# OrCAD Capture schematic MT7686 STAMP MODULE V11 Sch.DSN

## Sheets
1 10_BB_RF: size C; title: MT7686 Stamp Module; rev: 1.1; company: MediaTek Inc.; note: 10_BB_RF
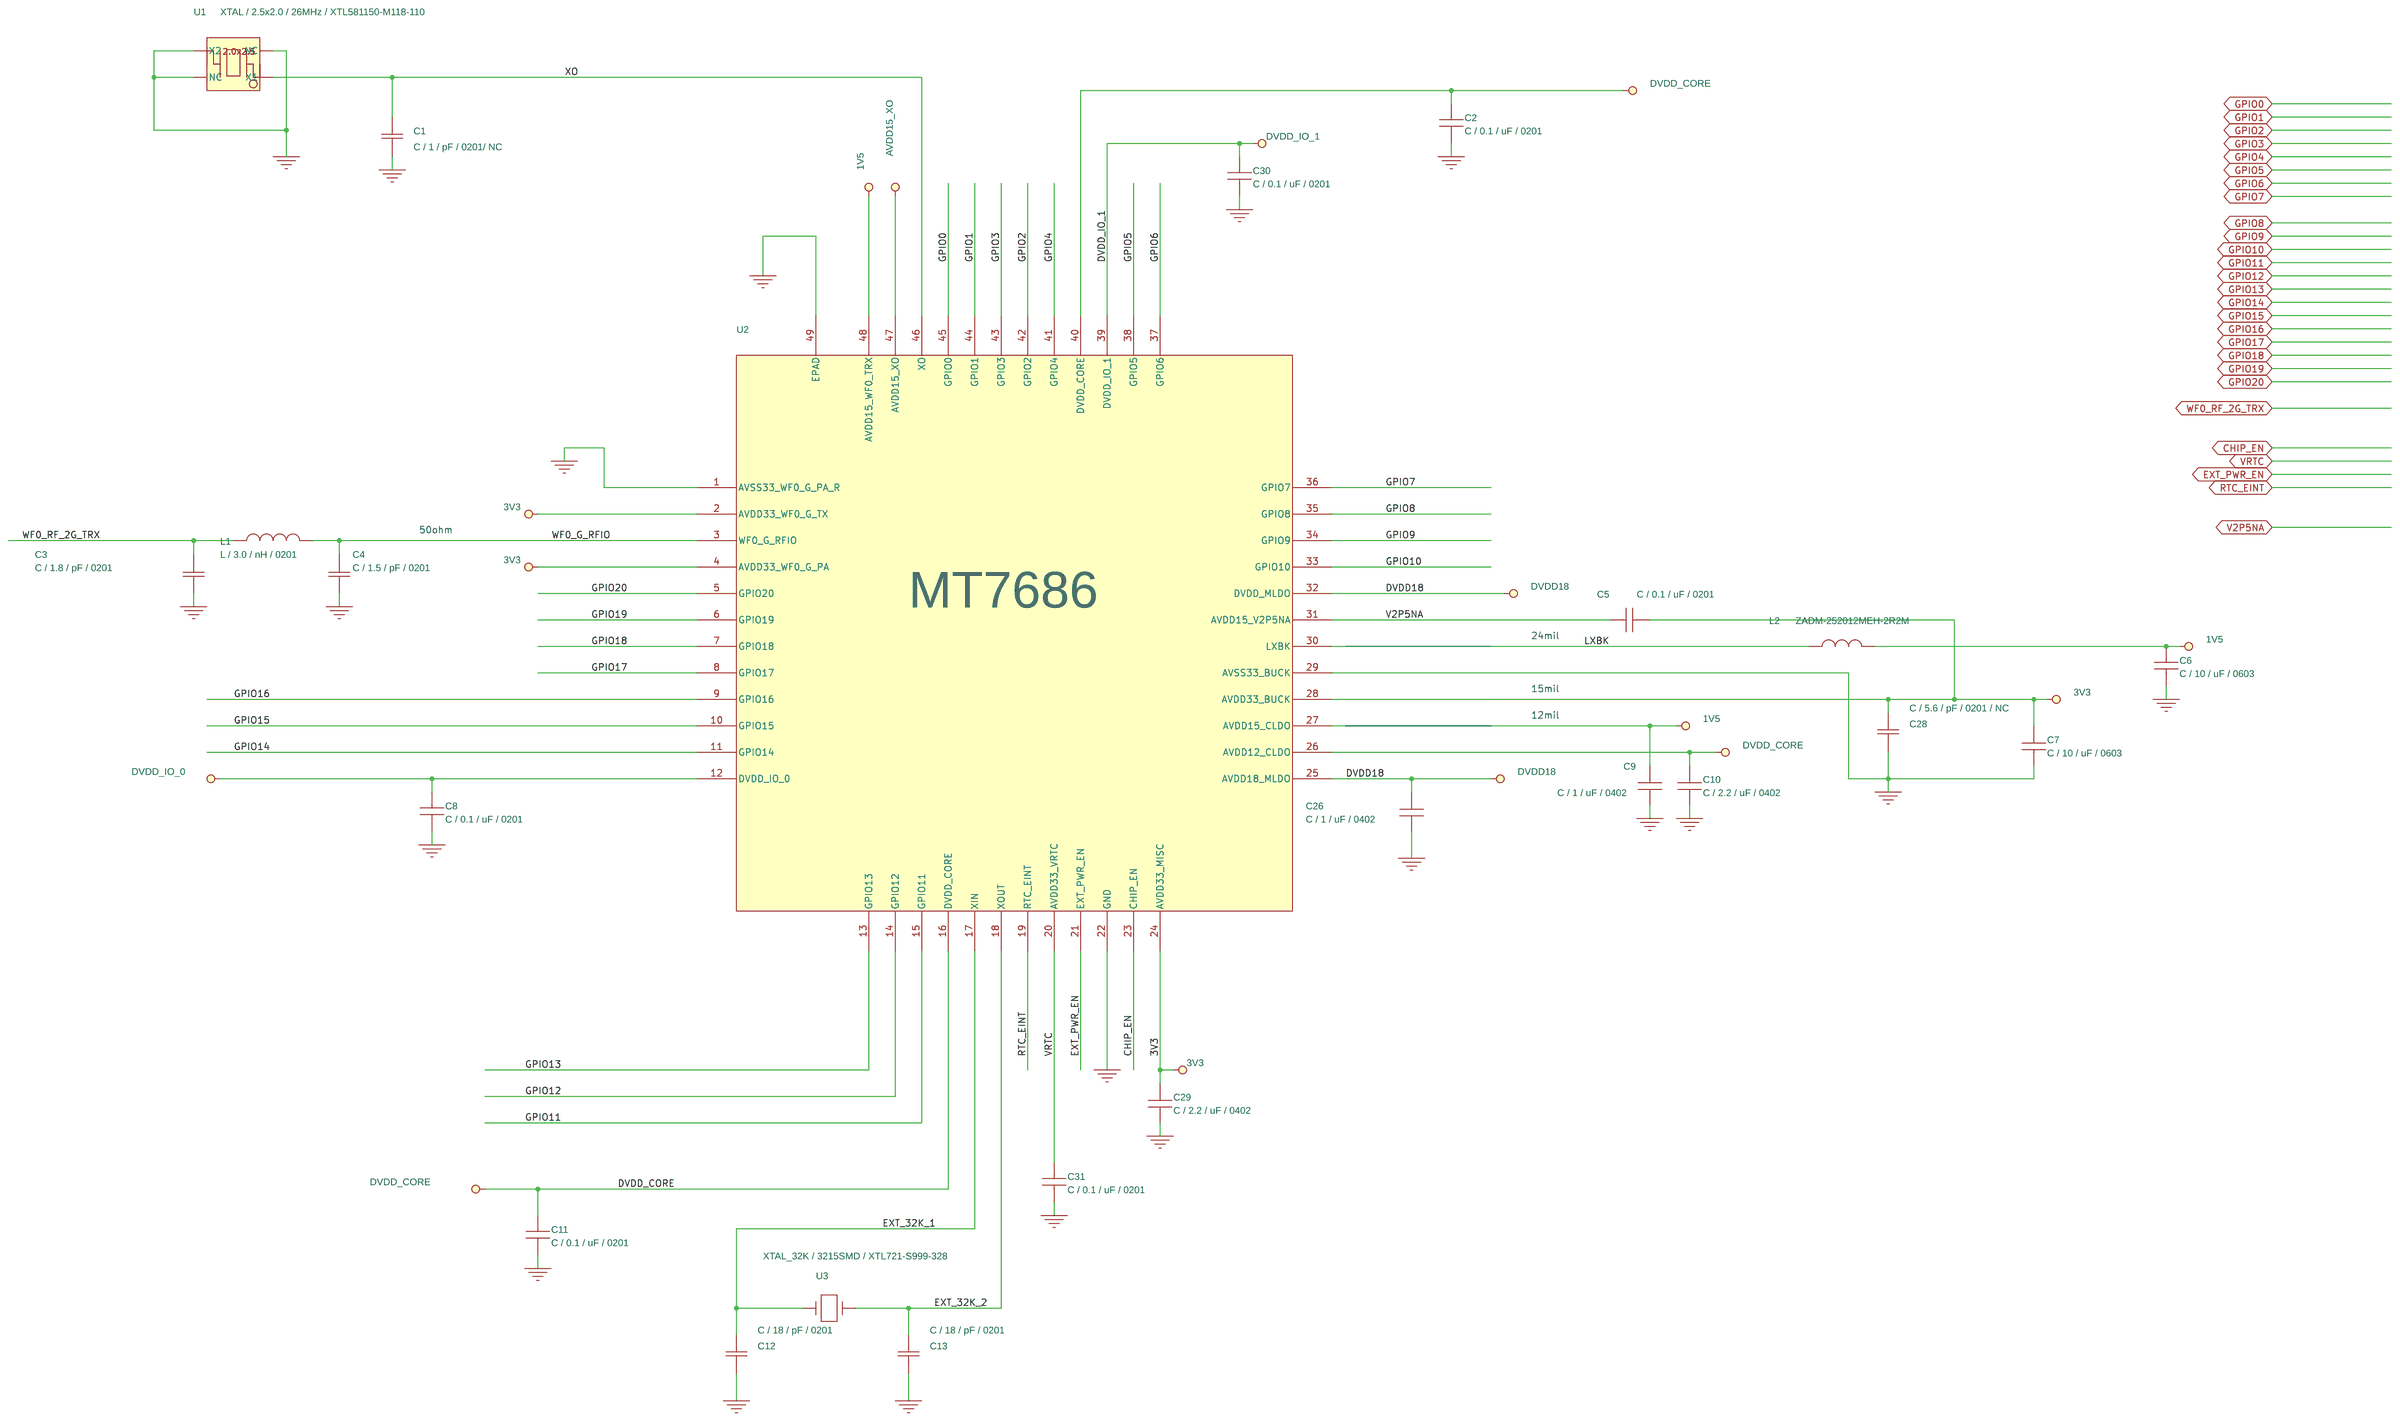
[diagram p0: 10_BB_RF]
2 20_RF Antenna and Connector: size C; note: 20_RF Antenna and Connector
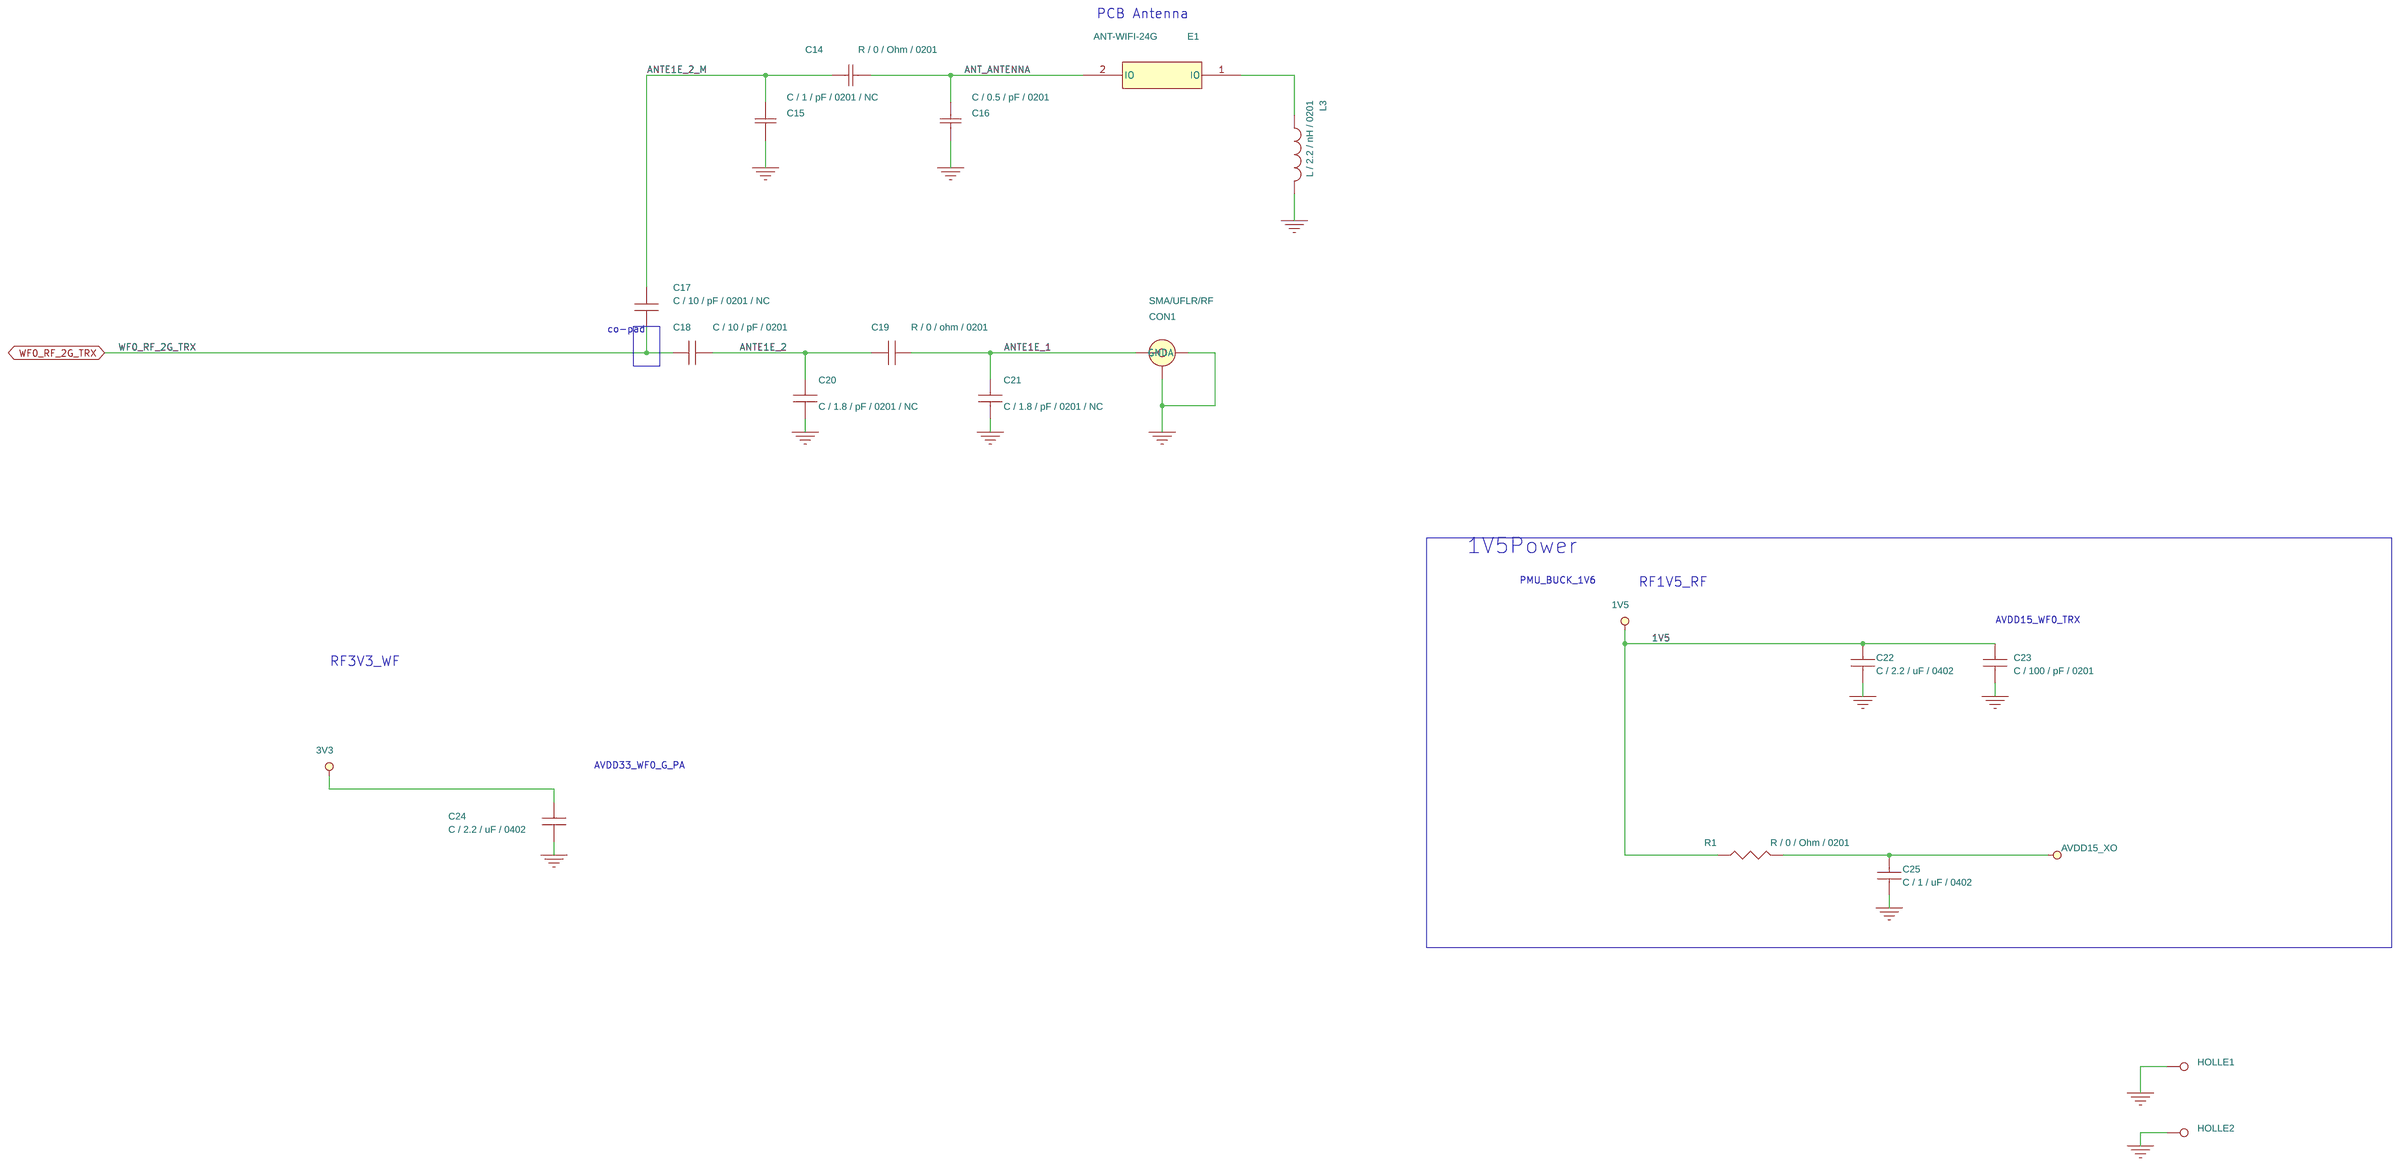
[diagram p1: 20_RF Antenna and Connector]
3 21_Strap and Module: size C; note: 21_Strap and Module
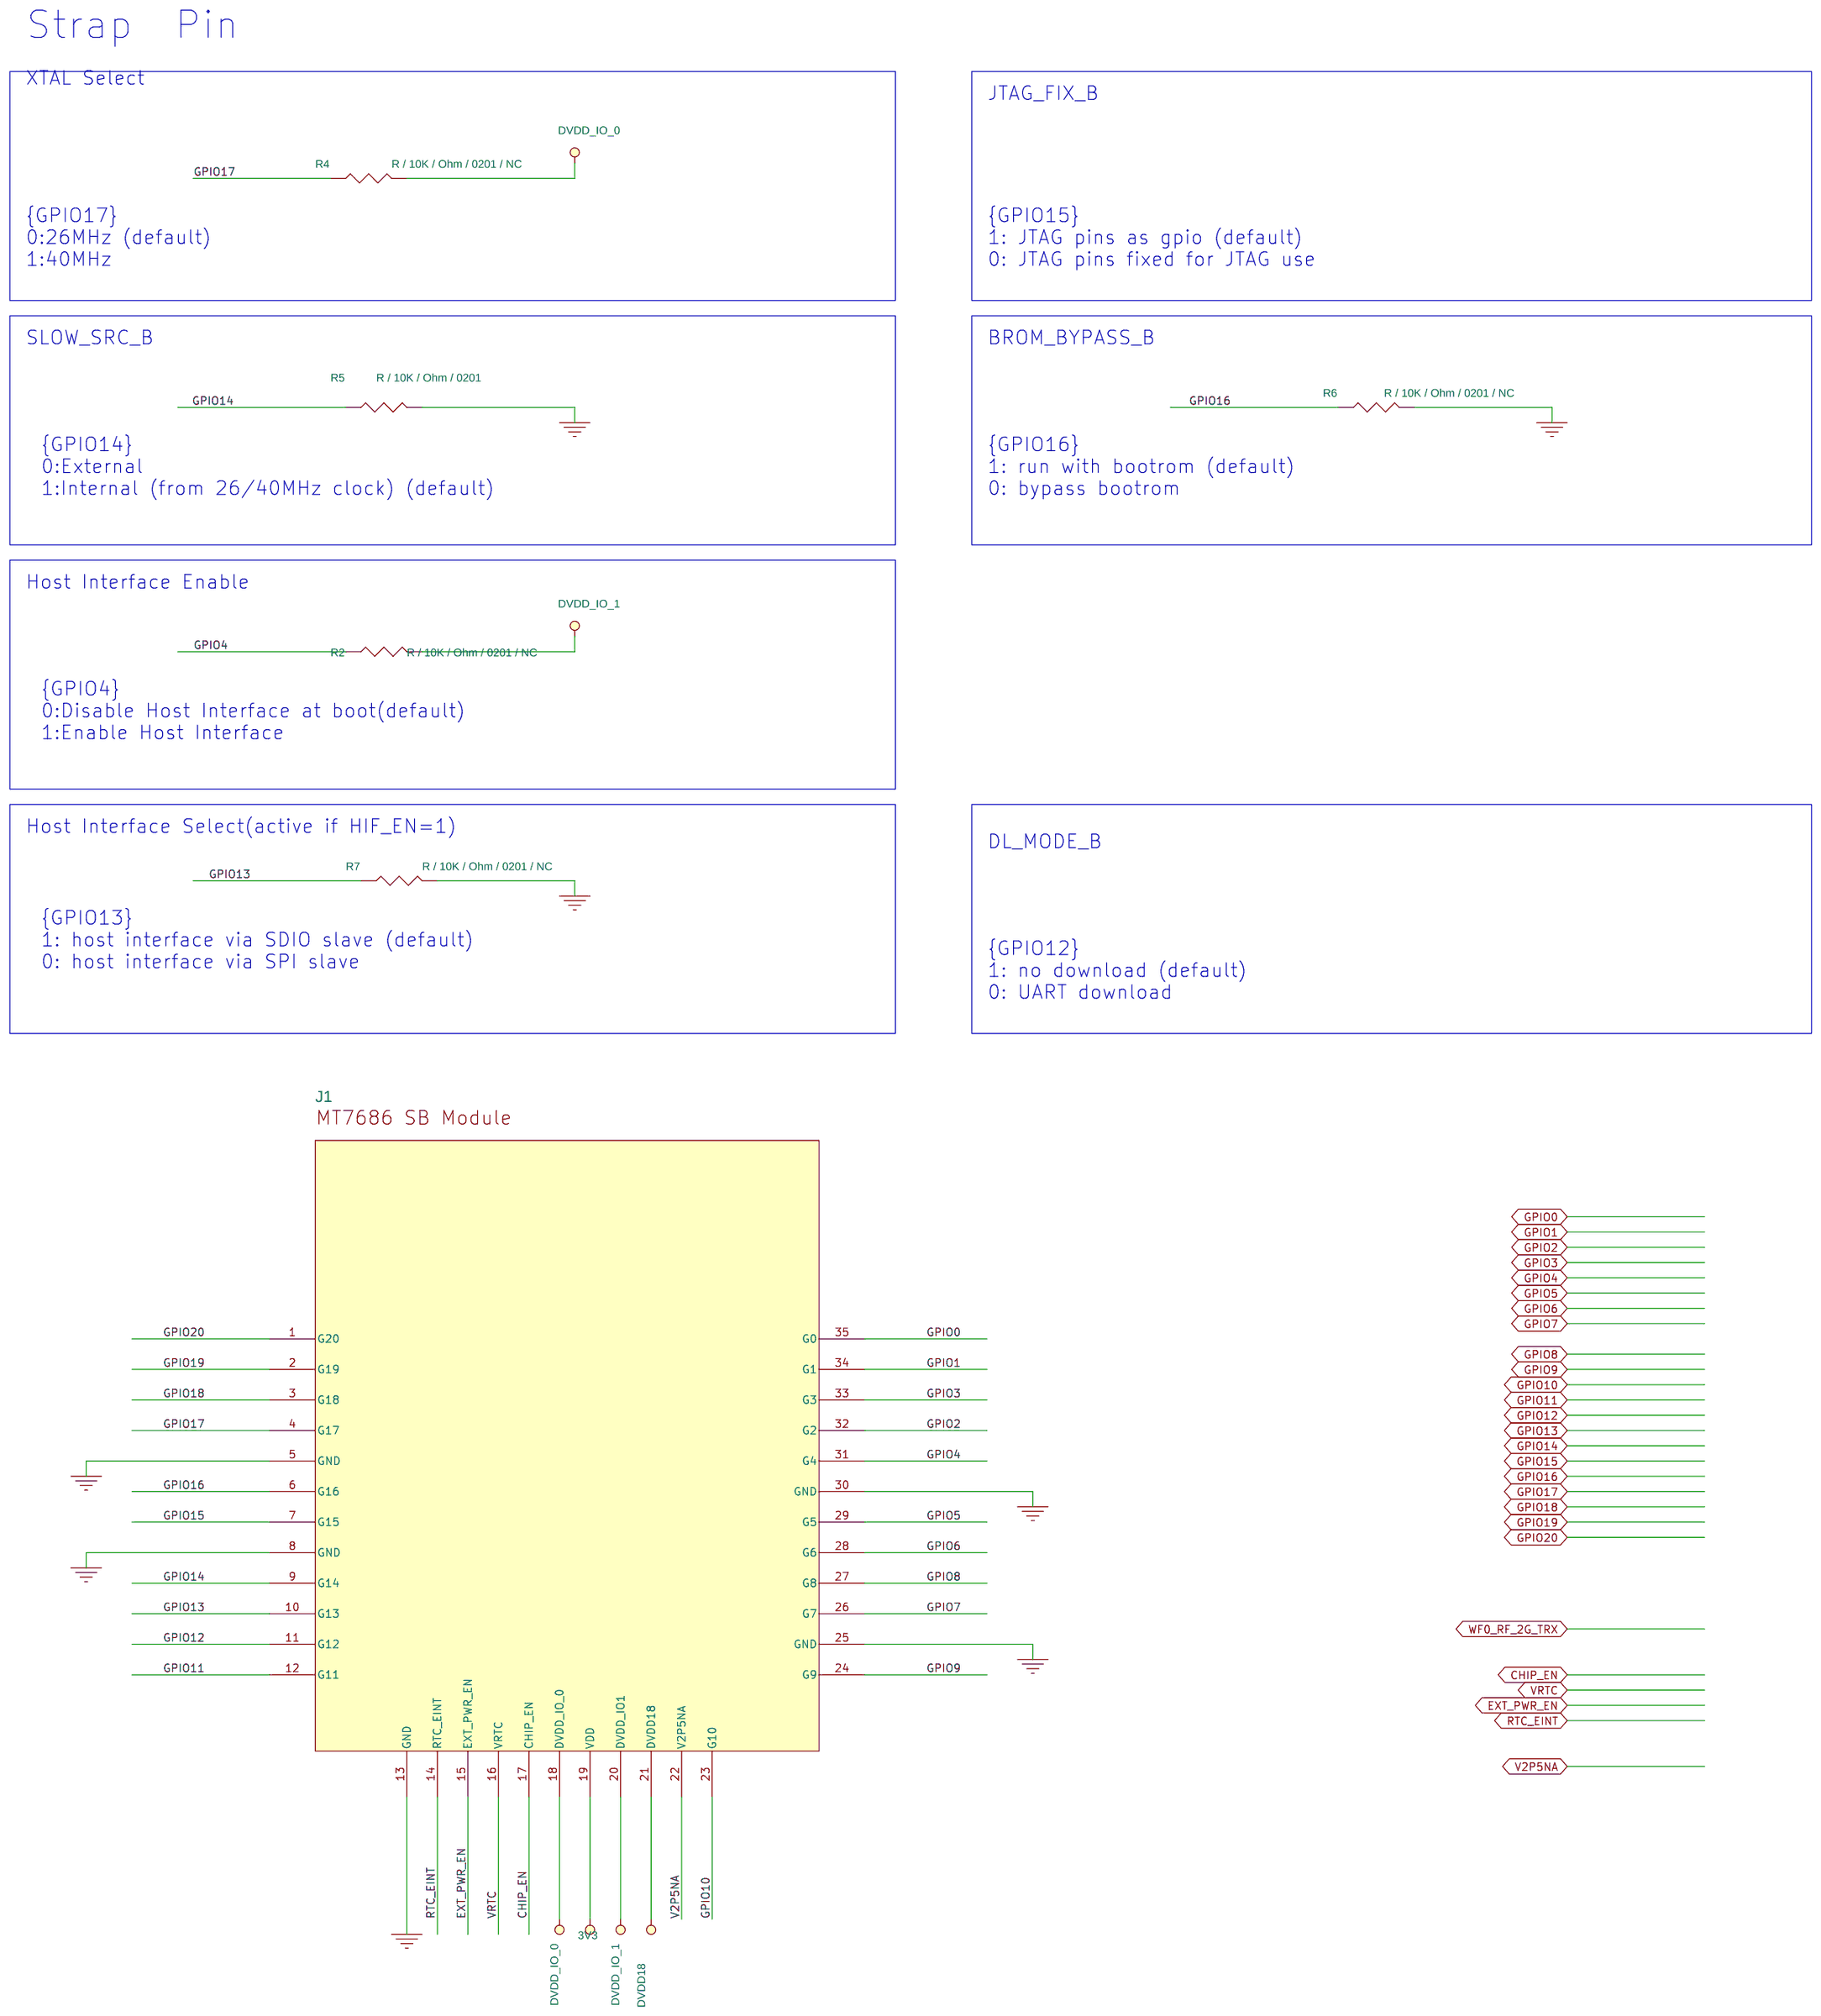
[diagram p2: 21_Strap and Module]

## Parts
sheet 10_BB_RF
C1  C / 1 / pF / 0201/ NC  [C0201]
C2  C / 0.1 / uF / 0201  [C0201]
C3  C / 1.8 / pF / 0201  [C0201]
C4  C / 1.5 / pF / 0201  [C0201]
C5  C / 0.1 / uF / 0201  [C0201]
C6  C / 10 / uF / 0603  [C0603]
C7  C / 10 / uF / 0603  [C0603]
C8  C / 0.1 / uF / 0201  [C0201]
C9  C / 1 / uF / 0402  [C0402]
C10  C / 2.2 / uF / 0402  [C0402]
C11  C / 0.1 / uF / 0201  [C0201]
C12  C / 18 / pF / 0201  [C0201]
C13  C / 18 / pF / 0201  [C0201]
C26  C / 1 / uF / 0402  [C0402]
C28  C / 5.6 / pF / 0201 / NC  [C0201]
C29  C / 2.2 / uF / 0402  [C0402]
C30  C / 0.1 / uF / 0201  [C0201]
C31  C / 0.1 / uF / 0201  [C0201]
L1  L / 3.0 / nH / 0201  [L0201]
L2  ZADM-252012MEH-2R2M  [L/IND/SMD/VLS252012E]
U1  XTAL / 2.5x2.0 / 26MHz / XTL581150-M118-110  [CRYS/SMD/2.5X2.0/CT2520DB/KYOCERA]
U2  MT7686  [MT7686/SQFN48/SMD/P0.4/6X6]
U3  XTAL_32K / 3215SMD / XTL721-S999-328  [RTC/SMD/2P/3.2X1.5]
sheet 20_RF Antenna and Connector
C14  R / 0 / Ohm / 0201  [C0201]
C15  C / 1 / pF / 0201 / NC  [C0201]
C16  C / 0.5 / pF / 0201  [C0201]
C17  C / 10 / pF / 0201 / NC  [C0201]
C18  C / 10 / pF / 0201  [C0201]
C19  R / 0 / ohm / 0201  [C0201]
C20  C / 1.8 / pF / 0201 / NC  [C0201]
C21  C / 1.8 / pF / 0201 / NC  [C0201]
C22  C / 2.2 / uF / 0402  [C0402]
C23  C / 100 / pF / 0201  [C0201]
C24  C / 2.2 / uF / 0402  [C0402]
C25  C / 1 / uF / 0402  [C0402]
CON1  SMA/UFLR/RF  [COAXIAL/SMD/CON/V/I-PEX]
E1  ANT-WIFI-24G  [ANT/2P/SMD/MT7682/RF_1]
HOLLE1  TP-SMD  [HOLE/PTH/R1X1.5D0.6]
HOLLE2  TP-SMD  [HOLE/PTH/R1X1.5D0.6]
L3  L / 2.2 / nH / 0201  [L0201]
R1  R / 0 / Ohm / 0201  [R0201]
sheet 21_Strap and Module
J1  pin to pin module  [MODULE/35P/SMD/SB-MT7686]
R2  R / 10K / Ohm / 0201 / NC  [R0201]
R4  R / 10K / Ohm / 0201 / NC  [R0201]
R5  R / 10K / Ohm / 0201  [R0201]
R6  R / 10K / Ohm / 0201 / NC  [R0201]
R7  R / 10K / Ohm / 0201 / NC  [R0201]

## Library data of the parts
C1 C3 C4 C12-C16 C28 = CAP_0402
C2 C6 C8 C11 C22-C24 C30 C31 = CAPACITOR_NON-POL: PART_NUMBER: C21-0402M104Y1EWLS; PART_TYPE: C21
C5 = CAPACITOR_NON-POL: PART_NUMBER: C21-0402K102X1CWLS; PART_TYPE: C21
C7 C9 C10 C25 C26 C29 = C_0402
L1 L3 = INDUCTOR: PART_NUMBER: L42-0201S3N320ACX0; PART_TYPE: L42
L2 = L_2.5*2.0
U1 = XTAL_2.5
U2 = MT7662E-20121128_11
U3 = XTAL_49_U-SMD
C17-C19 = CAPACITOR_NON-POL: PART_NUMBER: C21-0201C3R9C1HTDK; PART_TYPE: C21
C20 = CAPACITOR_NON-POL: PART_NUMBER: C21-0201BR30C1HTDK; PART_TYPE: C21
C21 = CAPACITOR_NON-POL: PART_NUMBER: C21-0201BR30C1HTDK
CON1 = SMA_UFLR
E1 = ANT-25G-R-CB_0
HOLLE1 HOLLE2 = TP-SMD
R1 R2 R4-R7 = RESISTOR: PART_NUMBER: R31-0201J1003FWLS0; PART_TYPE: R31
J1 = S500_9

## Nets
1V5: C6.1 C9.2 C22.1 C23.1 L2.2 R1.2 U2.27(AVDD15_CLDO) U2.48(AVDD15_WF0_TRX)
3V3: C5.2 C7.2 C24.1 C28.1 C29.2 J1.19(VDD) U2.2(AVDD33_WF0_G_TX) U2.4(AVDD33_WF0_G_PA) U2.24(AVDD33_MISC) U2.28(AVDD33_BUCK)
AVDD15_XO: C25.2 R1.1 U2.47(AVDD15_XO)
DVDD18: C26.2 J1.21(DVDD18) U2.25(AVDD18_MLDO) U2.32(DVDD_MLDO)
DVDD_CORE: C2.1 C10.2 C11.1 U2.16(DVDD_CORE) U2.26(AVDD12_CLDO) U2.40(DVDD_CORE)
DVDD_IO_0: C8.1 J1.18(DVDD_IO_0) R4.1 U2.12(DVDD_IO_0)
DVDD_IO_1: C30.1 J1.20(DVDD_IO1) R2.1 U2.39(DVDD_IO_1)
GND: C1.2 C2.2 C3.1 C4.1 C6.2 C7.1 C8.2 C9.1 C10.1 C11.2 C12.2 C13.2 C15.2 C16.2 C20.2 C21.2 C22.2 C23.2 C24.2 C25.1 C26.1 C28.2 C29.1 C30.2 C31.2 CON1.2 CON1.3(GNDA) HOLLE1.1 HOLLE2.1 J1.5(GND) J1.8(GND) J1.13(GND) J1.25(GND) J1.30(GND) L3.1 R5.1 R6.1 R7.1 U1.2(NC) U1.3(X2) U1.4(NC) U2.1(AVSS33_WF0_G_PA_R) U2.22(GND) U2.29(AVSS33_BUCK) U2.49(EPAD)
V2P5NA: C5.1 J1.22(V2P5NA) U2.31(AVDD15_V2P5NA)
ANT_ANTENNA: C14.2 C16.1 E1.2(IO)
ANTE1E_1: C19.1 C21.1 CON1.1
ANTE1E_2: C18.2 C19.2 C20.1
ANTE1E_2_M: C14.1 C15.1 C17.2
CHIP_EN: J1.17(CHIP_EN) U2.23(CHIP_EN)
EXT_32K_1: C12.1 U2.17(XIN) U3.1
EXT_32K_2: C13.1 U2.18(XOUT) U3.2
EXT_PWR_EN: J1.15(EXT_PWR_EN) U2.21(EXT_PWR_EN)
GPIO0: J1.35(G0) U2.45(GPIO0)
GPIO1: J1.34(G1) U2.44(GPIO1)
GPIO2: J1.32(G2) U2.42(GPIO2)
GPIO3: J1.33(G3) U2.43(GPIO3)
GPIO4: J1.31(G4) R2.2 U2.41(GPIO4)
GPIO5: J1.29(G5) U2.38(GPIO5)
GPIO6: J1.28(G6) U2.37(GPIO6)
GPIO7: J1.26(G7) U2.36(GPIO7)
GPIO8: J1.27(G8) U2.35(GPIO8)
GPIO9: J1.24(G9) U2.34(GPIO9)
GPIO10: J1.23(G10) U2.33(GPIO10)
GPIO11: J1.12(G11) U2.15(GPIO11)
GPIO12: J1.11(G12) U2.14(GPIO12)
GPIO13: J1.10(G13) R7.2 U2.13(GPIO13)
GPIO14: J1.9(G14) R5.2 U2.11(GPIO14)
GPIO15: J1.7(G15) U2.10(GPIO15)
GPIO16: J1.6(G16) R6.2 U2.9(GPIO16)
GPIO17: J1.4(G17) R4.2 U2.8(GPIO17)
GPIO18: J1.3(G18) U2.7(GPIO18)
GPIO19: J1.2(G19) U2.6(GPIO19)
GPIO20: J1.1(G20) U2.5(GPIO20)
LXBK: L2.1 U2.30(LXBK)
RTC_EINT: J1.14(RTC_EINT) U2.19(RTC_EINT)
VRTC: C31.1 J1.16(VRTC) U2.20(AVDD33_VRTC)
WF0_G_RFIO: C4.2 L1.1 U2.3(WF0_G_RFIO)
WF0_RF_2G_TRX: C3.2 C17.1 C18.1 L1.2
XO: C1.1 U1.1(X1) U2.46(XO)
N15633417: E1.1(IO) L3.2

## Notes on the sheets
sheet 1
- 50ohm
- 24mil
- 15mil
- 12mil
sheet 2
- PCB Antenna
- co-pad
- 1V5Power
- PMU_BUCK_1V6
- RF1V5_RF
- AVDD15_WF0_TRX
- RF3V3_WF
- AVDD33_WF0_G_PA
sheet 3
- Strap  Pin
- XTAL Select
- JTAG_FIX_B
- {GPIO17}
  0:26MHz (default)
  1:40MHz
- {GPIO15}
  1: JTAG pins as gpio (default)
  0: JTAG pins fixed for JTAG use
- SLOW_SRC_B
- BROM_BYPASS_B
- {GPIO14}
  0:External
  1:Internal (from 26/40MHz clock) (default)
- {GPIO16}
  1: run with bootrom (default)
  0: bypass bootrom
- Host Interface Enable
- {GPIO4}
  0:Disable Host Interface at boot(default)
  1:Enable Host Interface
- Host Interface Select(active if HIF_EN=1)
- DL_MODE_B
- {GPIO13}
  1: host interface via SDIO slave (default)
  0: host interface via SPI slave
- {GPIO12}
  1: no download (default)
  0: UART download
